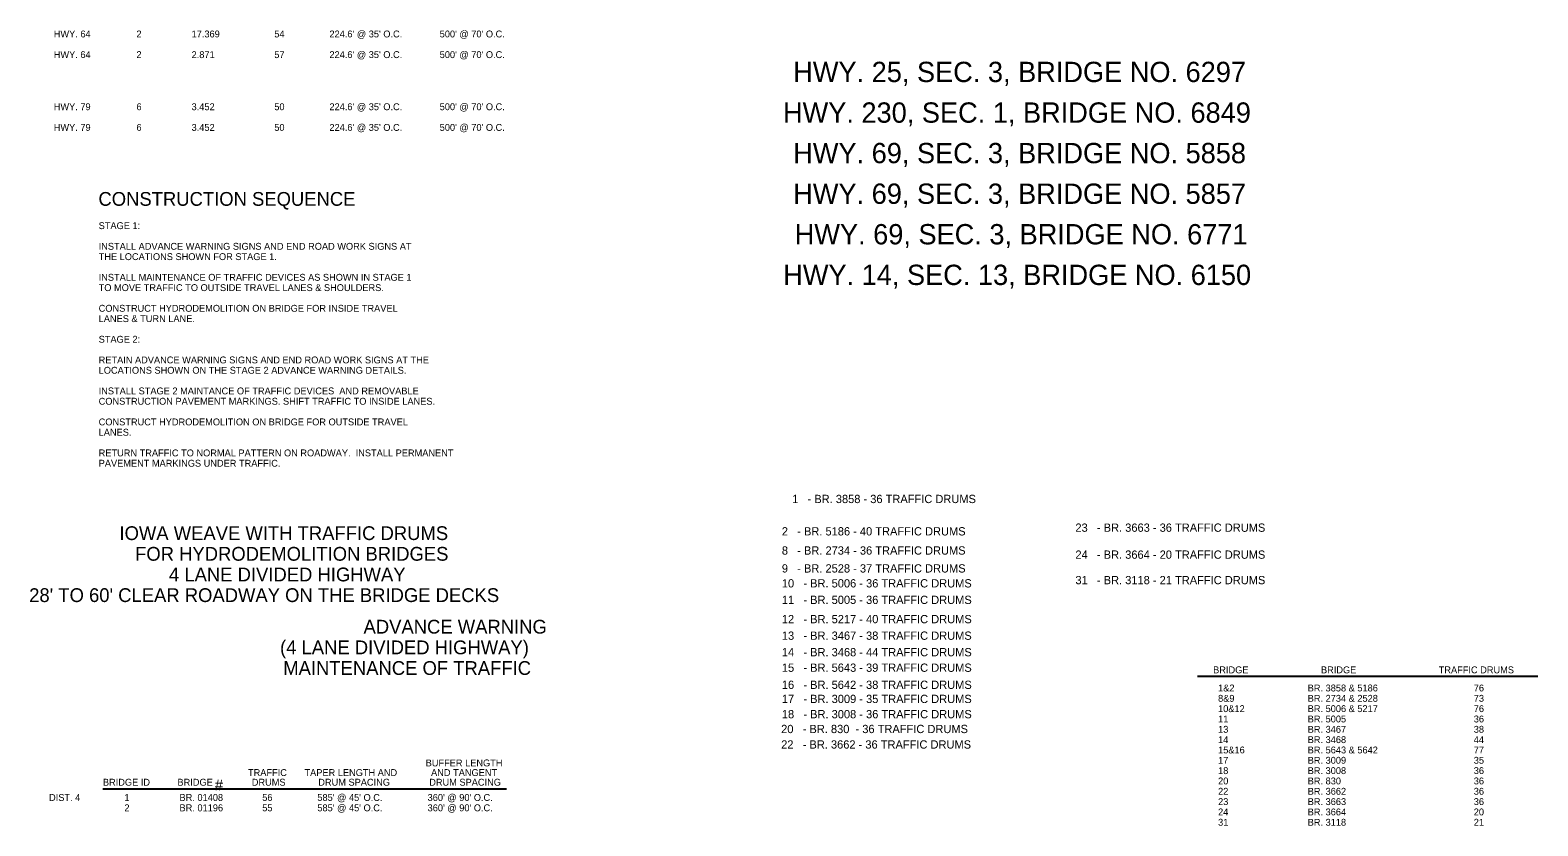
# Model space of a CAD drawing. Extents: x 1930579 to 1937521, y 596183 to 597566.
# Drawn here: x 1936208 to 1937521, y 596183 to 596876 of the extents above; entities that cross this region are included whole.
import ezdxf

# ---------------------------------------------------------------- set-up
doc = ezdxf.new("R2010")
doc.units = 0
doc.layers.add('Default', color=7, linetype='Continuous')
doc.layers.add('R_Annotation', color=7, linetype='Continuous')

msp = doc.modelspace()

# ---------------------------------------------------------------- linework, layer by layer
at = {"layer": 'R_Annotation'}
for p, q in [((1937224.8, 596313.5), (1937521.1, 596313.5)), ((1936271.8, 596215.4), (1936623.1, 596215.4))]:
    msp.add_line(p, q, dxfattribs=at)

# ---------------------------------------------------------------- texts
at = {"layer": 'Default'}
for s, p in [('HWY. 25, SEC. 3, BRIDGE NO. 6297', (1936872.8, 596831.1)), ('HWY. 230, SEC. 1, BRIDGE NO. 6849', (1936863.9, 596795.7)), ('HWY. 69, SEC. 3, BRIDGE NO. 5858', (1936872.8, 596760.4)), ('HWY. 69, SEC. 3, BRIDGE NO. 5857', (1936872.8, 596725)), ('HWY. 69, SEC. 3, BRIDGE NO. 6771', (1936874.1, 596689.7)), ('HWY. 14, SEC. 13, BRIDGE NO. 6150', (1936864.1, 596654.3))]:
    msp.add_text(s, height=17.682, rotation=360, dxfattribs=at).set_placement(p)
for s, p in [('IOWA WEAVE WITH TRAFFIC DRUMS', (1936286.2, 596432.1)), ('FOR HYDRODEMOLITION BRIDGES', (1936299.8, 596414.1)), ('4 LANE DIVIDED HIGHWAY', (1936329.3, 596396.1)), ("28' TO 60' CLEAR ROADWAY ON THE BRIDGE DECKS", (1936207.6, 596378.1))]:
    msp.add_text(s, height=12, dxfattribs=at).set_placement(p)
at = {"layer": 'R_Annotation'}
for s, height, p in [('HWY. 64', 6, (1936229, 596870)), ('2', 6, (1936301, 596870)), ('17.369', 6, (1936349, 596870)), ('54', 6, (1936421, 596870)), ("224.6' @ 35' O.C.", 6, (1936469, 596870)), ("500' @ 70' O.C.", 6, (1936565, 596870)), ('HWY. 64', 6, (1936229, 596852)), ('2', 6, (1936301, 596852)), ('2.871', 6, (1936349, 596852)), ('57', 6, (1936421, 596852)), ("224.6' @ 35' O.C.", 6, (1936469, 596852)), ("500' @ 70' O.C.", 6, (1936565, 596852)), ('HWY. 79', 6, (1936229, 596806.6)), ('6', 6, (1936301, 596806.6)), ('3.452', 6, (1936349, 596806.6)), ('50', 6, (1936421, 596806.6)), ("224.6' @ 35' O.C.", 6, (1936469, 596806.6)), ("500' @ 70' O.C.", 6, (1936565, 596806.6)), ('HWY. 79', 6, (1936229, 596788.6)), ('6', 6, (1936301, 596788.6)), ('3.452', 6, (1936349, 596788.6)), ('50', 6, (1936421, 596788.6)), ("224.6' @ 35' O.C.", 6, (1936469, 596788.6)), ("500' @ 70' O.C.", 6, (1936565, 596788.6)), ('CONSTRUCTION SEQUENCE', 12, (1936267.9, 596723.3)), ('STAGE 1:', 6, (1936268.1, 596703)), ('INSTALL ADVANCE WARNING SIGNS AND END ROAD WORK SIGNS AT', 6, (1936268.1, 596685)), ('THE LOCATIONS SHOWN FOR STAGE 1.', 6, (1936268.1, 596676)), ('TO MOVE TRAFFIC TO OUTSIDE TRAVEL LANES & SHOULDERS.', 6, (1936268.1, 596649)), ('INSTALL MAINTENANCE OF TRAFFIC DEVICES AS SHOWN IN STAGE 1', 6, (1936268.1, 596658)), ('CONSTRUCT HYDRODEMOLITION ON BRIDGE FOR INSIDE TRAVEL', 6, (1936268.1, 596631)), ('LANES & TURN LANE.', 6, (1936268.1, 596622)), ('STAGE 2:', 6, (1936268.1, 596604)), ('RETAIN ADVANCE WARNING SIGNS AND END ROAD WORK SIGNS AT THE', 6, (1936268.1, 596586)), ('LOCATIONS SHOWN ON THE STAGE 2 ADVANCE WARNING DETAILS.', 6, (1936268.1, 596577)), ('INSTALL STAGE 2 MAINTANCE OF TRAFFIC DEVICES  AND REMOVABLE', 6, (1936268.1, 596559)), ('CONSTRUCTION PAVEMENT MARKINGS. SHIFT TRAFFIC TO INSIDE LANES.', 6, (1936268.1, 596550)), ('CONSTRUCT HYDRODEMOLITION ON BRIDGE FOR OUTSIDE TRAVEL', 6, (1936268.1, 596532)), ('LANES.', 6, (1936268.1, 596523)), ('RETURN TRAFFIC TO NORMAL PATTERN ON ROADWAY.  INSTALL PERMANENT', 6, (1936268.1, 596505)), ('PAVEMENT MARKINGS UNDER TRAFFIC.', 6, (1936268.1, 596496)), ('1   - BR. 3858 - 36 TRAFFIC DRUMS', 7.2, (1936871.9, 596464.3)), ('2   - BR. 5186 - 40 TRAFFIC DRUMS', 7.2, (1936862.9, 596436.1)), ('23   - BR. 3663 - 36 TRAFFIC DRUMS', 7.2, (1937118.5, 596439.3)), ('8   - BR. 2734 - 36 TRAFFIC DRUMS', 7.2, (1936862.9, 596419.4)), ('24   - BR. 3664 - 20 TRAFFIC DRUMS', 7.2, (1937118.5, 596415.8)), ('9   - BR. 2528 - 37 TRAFFIC DRUMS', 7.2, (1936862.9, 596403.8)), ('10   - BR. 5006 - 36 TRAFFIC DRUMS', 7.2, (1936862.9, 596390.8)), ('31   - BR. 3118 - 21 TRAFFIC DRUMS', 7.2, (1937118.5, 596393.6)), ('11   - BR. 5005 - 36 TRAFFIC DRUMS', 7.2, (1936862.9, 596376.4)), ('ADVANCE WARNING ', 12, (1936498.7, 596350.6)), ('12   - BR. 5217 - 40 TRAFFIC DRUMS', 7.2, (1936862.9, 596359.6)), ('13   - BR. 3467 - 38 TRAFFIC DRUMS', 7.2, (1936862.9, 596345.2)), ('(4 LANE DIVIDED HIGHWAY)', 12, (1936426, 596332.6)), ('14   - BR. 3468 - 44 TRAFFIC DRUMS', 7.2, (1936862.9, 596330.8)), ('MAINTENANCE OF TRAFFIC', 12, (1936428.8, 596314.6)), ('15   - BR. 5643 - 39 TRAFFIC DRUMS', 7.2, (1936862.9, 596317.3)), ('BRIDGE ', 6, (1937238.4, 596316)), ('BRIDGE ', 6, (1937332.3, 596316)), ('TRAFFIC DRUMS', 6, (1937434.8, 596316)), ('16   - BR. 5642 - 38 TRAFFIC DRUMS', 7.2, (1936862.9, 596302.4)), ('17   - BR. 3009 - 35 TRAFFIC DRUMS', 7.2, (1936862.9, 596290.1)), ('8&9', 6, (1937242.7, 596291.2)), ('1&2', 6, (1937242.7, 596300.2)), ('BR. 3858 & 5186', 6, (1937320.7, 596300.2)), ('BR. 2734 & 2528', 6, (1937320.7, 596291.2)), ('76', 6, (1937465.3, 596300.2)), ('73', 6, (1937465.3, 596291.2)), ('18   - BR. 3008 - 36 TRAFFIC DRUMS', 7.2, (1936862.9, 596276.8)), ('10&12', 6, (1937242.7, 596282.2)), ('BR. 5006 & 5217', 6, (1937320.7, 596282.2)), ('76', 6, (1937465.3, 596282.2)), ('20   - BR. 830  - 36 TRAFFIC DRUMS', 7.2, (1936862.3, 596263.9)), ('11', 6, (1937242.7, 596273.2)), ('BR. 5005', 6, (1937320.7, 596273.2)), ('36', 6, (1937465.3, 596273.2)), ('22   - BR. 3662 - 36 TRAFFIC DRUMS', 7.2, (1936862.3, 596250.4)), ('13', 6, (1937242.7, 596264.2)), ('14', 6, (1937242.7, 596255.2)), ('BR. 3467', 6, (1937320.7, 596264.2)), ('BR. 3468', 6, (1937320.7, 596255.2)), ('44', 6, (1937465.3, 596255.2)), ('38', 6, (1937465.3, 596264.2)), ('15&16', 6, (1937242.7, 596246.2)), ('BR. 5643 & 5642', 6, (1937320.7, 596246.2)), ('77', 6, (1937465.3, 596246.2)), ('TRAFFIC', 6, (1936398.1, 596226.5)), ('TAPER LENGTH AND', 6, (1936447.3, 596226.5)), ('BUFFER LENGTH', 6, (1936552.8, 596234.9)), ('AND TANGENT', 6, (1936557.5, 596226.5)), ('17', 6, (1937242.7, 596237.2)), ('18', 6, (1937242.7, 596228.2)), ('BR. 3009', 6, (1937320.7, 596237.2)), ('BR. 3008', 6, (1937320.7, 596228.2)), ('35', 6, (1937465.3, 596237.2)), ('36', 6, (1937465.3, 596228.2)), ('BRIDGE ID', 6, (1936271.8, 596218.1)), ('BRIDGE ', 6, (1936336.7, 596218.1)), ('#', 9.6, (1936369.2, 596213.9)), ('DRUMS', 6, (1936401.4, 596218.1)), ('DRUM SPACING', 6, (1936459.3, 596218.1)), ('DRUM SPACING', 6, (1936555.9, 596218.1)), ('20', 6, (1937242.7, 596219.2)), ('BR. 830', 6, (1937320.7, 596219.2)), ('36', 6, (1937465.3, 596219.2)), ('DIST. 4', 6, (1936224.9, 596204.8)), ('1', 6, (1936290.5, 596204.8)), ('BR. 01408', 6, (1936338.5, 596204.8)), ('56', 6, (1936410.5, 596204.8)), ("585' @ 45' O.C.", 6, (1936458.5, 596204.8)), ("360' @ 90' O.C.", 6, (1936554.5, 596204.8)), ('22', 6, (1937242.7, 596210.2)), ('23', 6, (1937242.7, 596201.2)), ('BR. 3662', 6, (1937320.7, 596210.2)), ('BR. 3663', 6, (1937320.7, 596201.2)), ('36', 6, (1937465.3, 596210.2)), ('36', 6, (1937465.3, 596201.2)), ('2', 6, (1936290.5, 596195.8)), ('BR. 01196', 6, (1936338.5, 596195.8)), ('55', 6, (1936410.5, 596195.8)), ("585' @ 45' O.C.", 6, (1936458.5, 596195.8)), ("360' @ 90' O.C.", 6, (1936554.5, 596195.8)), ('24', 6, (1937242.7, 596192.2)), ('BR. 3664', 6, (1937320.7, 596192.2)), ('20', 6, (1937465.3, 596192.2)), ('31', 6, (1937242.7, 596183.2)), ('BR. 3118', 6, (1937320.7, 596183.2)), ('21', 6, (1937465.3, 596183.2))]:
    msp.add_text(s, height=height, rotation=360, dxfattribs=at).set_placement(p)

doc.saveas('drawing.dxf')
